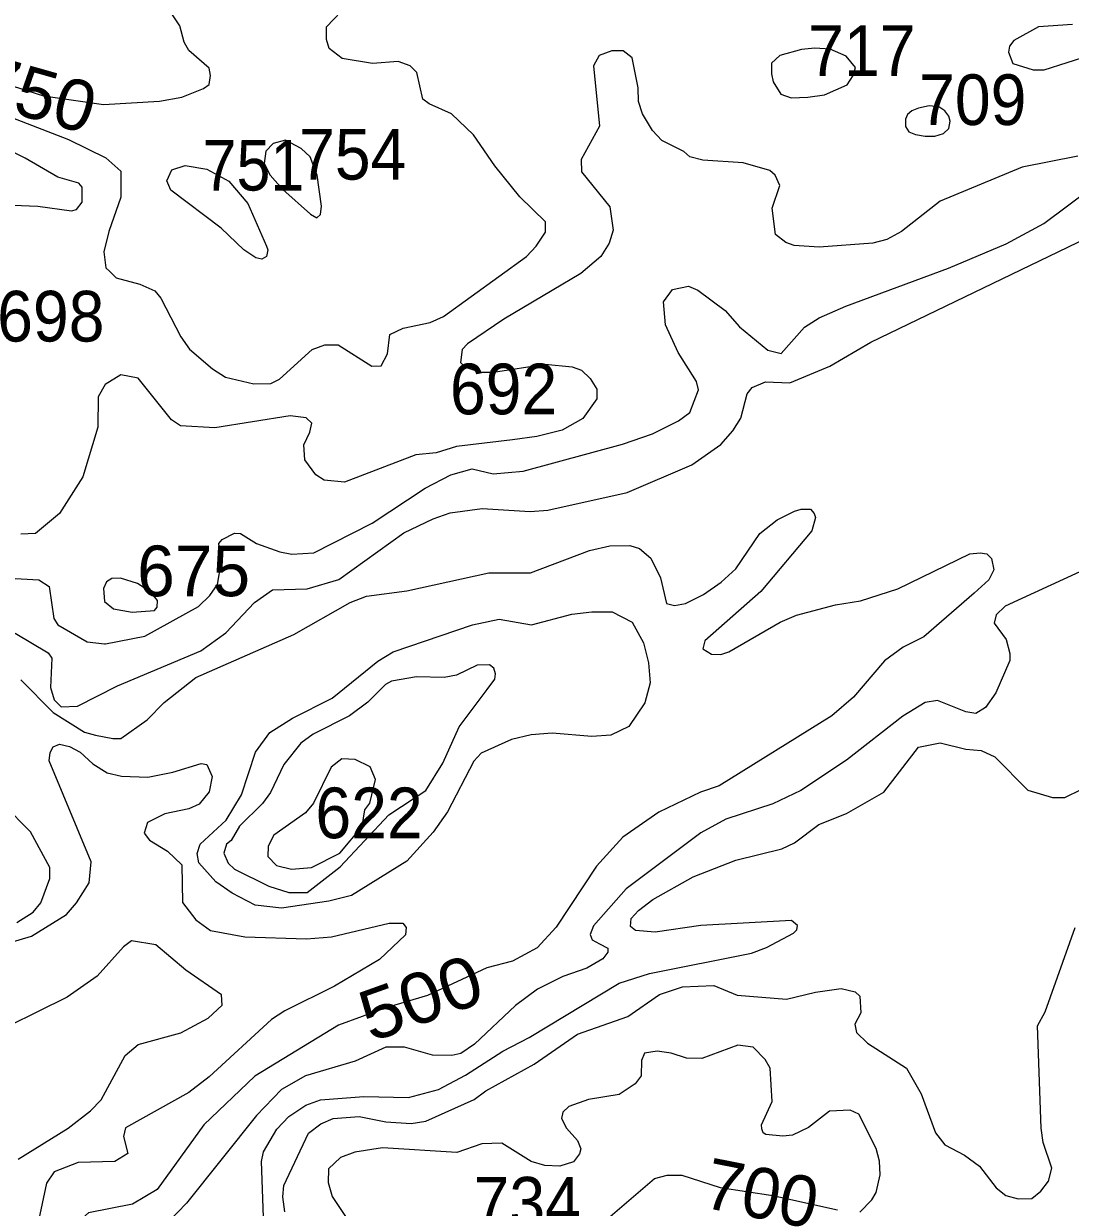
# Model space of a CAD drawing. Extents: x 499.9 to 555.3, y 9281.5 to 9336.8.
# Drawn here: x 539.393 to 542.701, y 9298.961 to 9302.7 of the extents above; entities that cross this region are included whole.
import ezdxf
from ezdxf.enums import TextEntityAlignment as Align

# ---------------------------------------------------------------- set-up
doc = ezdxf.new("R2010")
doc.units = 0
doc.header["$LTSCALE"] = 0.064
doc.layers.add('1', color=7, linetype='Continuous', lineweight=25)
doc.layers.add('2', color=7, linetype='Continuous', lineweight=13)
doc.layers.add('21', color=7, linetype='Continuous')
doc.layers.add('61', color=7, linetype='Continuous')

msp = doc.modelspace()

# ---------------------------------------------------------------- linework, layer by layer
at = {"layer": '1'}
for points in [[(539.3094, 9302.5175), (539.4558, 9302.4719), (539.6454, 9302.4446), (539.8226, 9302.4545), (539.8926, 9302.4671), (539.9617, 9302.4944), (539.9789, 9302.5073), (539.9835, 9302.5353), (539.9789, 9302.5594), (539.9155, 9302.6146), (539.9005, 9302.6411), (539.8868, 9302.6932), (539.8411, 9302.7602), (539.8248, 9302.8301), (539.7819, 9302.9001), (539.7231, 9302.959), (539.5872, 9303.0698), (539.529, 9303.131), (539.4177, 9303.2807), (539.3787, 9303.2971)], [(539.3846, 9300.6267), (539.4859, 9300.5243), (539.5854, 9300.4617), (539.6199, 9300.4526), (539.6745, 9300.4413), (539.7007, 9300.4421), (539.7835, 9300.5002), (539.837, 9300.5555), (539.937, 9300.6342), (540.2465, 9300.7702), (540.4251, 9300.8709), (540.476, 9300.8915), (540.604, 9300.9077), (540.8634, 9300.9646), (540.9948, 9300.965), (541.1807, 9301.0357), (541.2454, 9301.0506), (541.3091, 9301.0508), (541.3396, 9301.0423), (541.3755, 9301.0116), (541.4053, 9300.9489), (541.4245, 9300.8685), (541.4493, 9300.8617), (541.485, 9300.8679), (541.5413, 9300.8969), (541.597, 9300.9352), (541.6437, 9300.9777), (541.7197, 9301.0895), (541.7738, 9301.1323), (541.8294, 9301.1596), (541.8498, 9301.1659), (541.8799, 9301.166), (541.891, 9301.1526), (541.8952, 9301.1399), (541.8838, 9301.0979), (541.7221, 9300.9059), (541.5461, 9300.7504), (541.5398, 9300.7248), (541.5671, 9300.7076), (541.5957, 9300.7071), (541.6218, 9300.715), (541.7842, 9300.8089), (541.8352, 9300.8311), (541.9583, 9300.8637), (542.037, 9300.8761), (542.1558, 9300.914), (542.3827, 9301.0251), (542.4156, 9301.0283), (542.4364, 9301.0248), (542.4518, 9301.01), (542.4585, 9300.9744), (542.4431, 9300.9426), (542.3969, 9300.9012), (542.2378, 9300.7625), (542.1719, 9300.7304), (542.1131, 9300.6873), (542.0154, 9300.5724), (541.9472, 9300.5134), (541.5907, 9300.2922), (541.532, 9300.2722), (541.3998, 9300.2092), (541.2867, 9300.1298), (541.2033, 9300.0385), (541.0756, 9299.8462), (541.0162, 9299.7804), (540.9382, 9299.7382), (540.8569, 9299.7175), (540.6693, 9299.6305), (540.5379, 9299.5915), (540.388, 9299.5367), (540.1236, 9299.3757)], [(539.3714, 9299.8604), (539.4231, 9299.8933), (539.4476, 9299.9225), (539.476, 9299.9996), (539.4761, 9300.0338), (539.4152, 9300.1465), (539.329, 9300.2329)], [(540.1236, 9299.3757), (539.9621, 9299.2217), (539.8153, 9299.0169), (539.7366, 9298.9706), (539.5983, 9298.9436), (539.5418, 9298.8941)]]:
    msp.add_lwpolyline(points, dxfattribs=at)
for points in [[(540.2126, 9302.1754), (540.2991, 9302.0978), (540.3195, 9302.0866), (540.3314, 9302.0973), (540.3342, 9302.1228), (540.3205, 9302.2212), (540.298, 9302.2789), (540.2704, 9302.3049), (540.2208, 9302.3312), (540.1818, 9302.3212), (540.1587, 9302.2969), (540.1532, 9302.2579), (540.1725, 9302.2213)], [(540.0174, 9302.0538), (539.8579, 9302.174), (539.8457, 9302.2035), (539.8619, 9302.2374), (539.9032, 9302.2512), (539.9719, 9302.2396), (540.0415, 9302.2016), (540.1011, 9302.1316), (540.1604, 9301.997), (540.1649, 9301.9853), (540.1605, 9301.9637), (540.1454, 9301.9556), (540.1265, 9301.9598), (540.0892, 9301.9853)], [(540.7323, 9300.2097), (540.6867, 9300.1464), (540.604, 9300.0548), (540.429, 9299.946), (540.3574, 9299.9277), (540.208, 9299.9058), (540.1245, 9299.9148), (540.052, 9299.9531), (540.0007, 9299.9888), (539.9467, 9300.049), (539.9414, 9300.0783), (539.951, 9300.1085), (540.0333, 9300.1839), (540.0817, 9300.2633), (540.1253, 9300.3987), (540.1715, 9300.4612), (540.2428, 9300.5059), (540.3677, 9300.5686), (540.5119, 9300.6858), (540.5603, 9300.7155), (540.8118, 9300.8009), (540.8961, 9300.8183), (540.9979, 9300.8012), (541.1254, 9300.8343), (541.1889, 9300.8423), (541.2526, 9300.8421), (541.3156, 9300.8091), (541.3514, 9300.7444), (541.3673, 9300.6807), (541.3733, 9300.6179), (541.3559, 9300.5543), (541.305, 9300.4795), (541.2485, 9300.452), (541.1881, 9300.4478), (541.0637, 9300.4587), (540.9971, 9300.4537), (540.9351, 9300.4382), (540.8389, 9300.3949), (540.8161, 9300.3705)]]:
    msp.add_lwpolyline(points, close=True, dxfattribs=at)
at = {"layer": '2'}
for points in [[(539.8899, 9301.7104), (539.9177, 9301.6715), (539.9904, 9301.6092), (540.0314, 9301.5833), (540.1202, 9301.5617), (540.1738, 9301.5633), (540.2021, 9301.5762), (540.3051, 9301.6709), (540.3447, 9301.6855), (540.3875, 9301.6853), (540.4936, 9301.6182), (540.5231, 9301.6191), (540.5427, 9301.6564), (540.55, 9301.7178), (540.5924, 9301.7378), (540.6779, 9301.7555), (540.7203, 9301.7746), (540.982, 9301.9644), (541.0127, 9301.9968), (541.0419, 9302.0412), (541.0425, 9302.0733), (540.9614, 9302.1522), (540.8823, 9302.2502), (540.8149, 9302.3479), (540.7448, 9302.4146), (540.6748, 9302.4458), (540.6548, 9302.4606), (540.6355, 9302.5455), (540.614, 9302.5664), (540.577, 9302.5802), (540.4958, 9302.574), (540.3996, 9302.59), (540.3588, 9302.6213), (540.3503, 9302.6495), (540.3506, 9302.69), (540.4186, 9302.7615)], [(542.7073, 9302.6967), (542.6, 9302.6897), (542.522, 9302.6462), (542.5083, 9302.6285), (542.5055, 9302.6098), (542.5189, 9302.5739), (542.5831, 9302.5534), (542.618, 9302.5533), (542.7632, 9302.5997)], [(542.724, 9302.2814), (542.5479, 9302.2462), (542.2894, 9302.1393), (542.1676, 9302.0433), (542.1209, 9302.0183), (542.077, 9302.0058), (541.9065, 9301.9931), (541.8274, 9301.9991), (541.8013, 9302.0086), (541.7689, 9302.034), (541.7589, 9302.1165), (541.7827, 9302.188), (541.7681, 9302.2206), (541.7505, 9302.2355), (541.6665, 9302.2597), (541.5391, 9302.2684), (541.4979, 9302.2787), (541.4794, 9302.2955), (541.4094, 9302.3301), (541.38, 9302.3623), (541.3491, 9302.4149), (541.3357, 9302.4538), (541.3352, 9302.4967), (541.3159, 9302.5913), (541.2874, 9302.6137), (541.2519, 9302.6134), (541.2121, 9302.5995), (541.1937, 9302.5661), (541.2127, 9302.3756), (541.1545, 9302.2706), (541.1554, 9302.2318), (541.2458, 9302.1208), (541.2555, 9302.0472), (541.2429, 9302.0058), (541.2175, 9301.9644), (541.1533, 9301.9105), (540.9104, 9301.766), (540.7957, 9301.6886), (540.7783, 9301.6708), (540.7731, 9301.6291), (540.7896, 9301.6143), (540.8364, 9301.5984), (540.8778, 9301.5985), (541.0407, 9301.6236), (541.1269, 9301.6153), (541.1556, 9301.6048), (541.1833, 9301.5787), (541.2046, 9301.5456), (541.2045, 9301.5141), (541.1605, 9301.4527), (541.0947, 9301.4153)], [(539.2537, 9302.4418), (539.5344, 9302.3332), (539.6524, 9302.276), (539.7, 9302.2334), (539.7, 9302.1513), (539.6621, 9302.043), (539.6466, 9301.979), (539.653, 9301.9284), (539.6639, 9301.9177)], [(539.3601, 9302.1267), (539.4375, 9302.1236), (539.5447, 9302.1081), (539.5597, 9302.1127), (539.5776, 9302.1359), (539.5782, 9302.1834), (539.5675, 9302.1953), (539.5012, 9302.2146), (539.3977, 9302.2751), (539.3156, 9302.3145)], [(539.3293, 9300.9493), (539.4406, 9300.9425), (539.4736, 9300.922), (539.4888, 9300.8204), (539.5011, 9300.8006), (539.5943, 9300.7471), (539.6483, 9300.7405), (539.6516, 9300.7406), (539.7757, 9300.7653), (539.9453, 9300.8586), (539.9818, 9300.8936), (540.0056, 9300.9279), (540.0174, 9300.996), (540.0101, 9301.0576), (540.0199, 9301.0702), (540.0589, 9301.0904), (540.0785, 9301.0897), (540.129, 9301.058), (540.2024, 9301.0309), (540.2404, 9301.0238), (540.3097, 9301.0285), (540.4944, 9301.1221), (540.662, 9301.2329), (540.7427, 9301.2749), (540.8103, 9301.2939), (540.8764, 9301.278), (540.9713, 9301.2857), (541.2852, 9301.371), (541.3799, 9301.4042), (541.4627, 9301.4456), (541.4978, 9301.4718), (541.526, 9301.5434), (541.5198, 9301.5696), (541.4618, 9301.6605), (541.4213, 9301.7487), (541.4152, 9301.821), (541.4436, 9301.8598), (541.4941, 9301.8705), (541.5233, 9301.8577), (541.6102, 9301.7939), (541.6553, 9301.7416), (541.7444, 9301.6681), (541.7872, 9301.6577), (541.8602, 9301.7409), (541.9067, 9301.7702), (541.9909, 9301.807), (542.3151, 9301.9275), (542.4979, 9302.0045), (542.6172, 9302.0683), (542.7669, 9302.1795)], [(540.5946, 9301.0917), (540.6874, 9301.136), (540.7409, 9301.1543), (540.8421, 9301.1685), (540.994, 9301.1591), (541.0497, 9301.1624), (541.2999, 9301.2186), (541.5043, 9301.3065), (541.5963, 9301.3708), (541.6346, 9301.4138), (541.659, 9301.4534), (541.6791, 9301.5307), (541.6957, 9301.5505), (541.7373, 9301.5678), (541.8143, 9301.5654), (541.9401, 9301.6175), (542.0707, 9301.6937), (542.7823, 9302.0369)], [(539.6639, 9301.9177), (539.685, 9301.897), (539.7607, 9301.8772), (539.8076, 9301.8553), (539.8268, 9301.8328), (539.8899, 9301.7104)], [(540.6324, 9301.3377), (540.4067, 9301.2516), (540.343, 9301.2573), (540.3163, 9301.2744), (540.2818, 9301.3222), (540.2788, 9301.3691), (540.2975, 9301.4089), (540.3036, 9301.4375), (540.2854, 9301.4544), (540.2354, 9301.4612), (539.9977, 9301.4233), (539.8884, 9301.4293), (539.8604, 9301.4486), (539.7554, 9301.58), (539.7003, 9301.5908), (539.6504, 9301.56), (539.6291, 9301.5213), (539.6271, 9301.4253), (539.5801, 9301.268), (539.5061, 9301.1521), (539.4302, 9301.0893), (539.3837, 9301.0871)], [(541.0947, 9301.4153), (541.0151, 9301.3952), (540.9382, 9301.3848), (540.7612, 9301.3638), (540.6966, 9301.3445), (540.6324, 9301.3377)], [(540.0316, 9300.7757), (540.1227, 9300.8711), (540.1799, 9300.9118), (540.2889, 9300.9142), (540.3893, 9300.9439), (540.5946, 9301.0917)], [(542.7302, 9300.9685), (542.4942, 9300.8597), (542.4661, 9300.8319), (542.4598, 9300.806), (542.4973, 9300.7539), (542.5098, 9300.7102), (542.5099, 9300.6879), (542.4653, 9300.5861), (542.4326, 9300.5397), (542.4019, 9300.5212), (542.37, 9300.5258), (542.2808, 9300.562), (542.2418, 9300.5554), (542.1708, 9300.5122), (541.9934, 9300.3732), (541.8495, 9300.2771), (541.76, 9300.2356), (541.6124, 9300.1865), (541.533, 9300.1433), (541.297, 9299.9664), (541.1935, 9299.85), (541.1829, 9299.8223), (541.1896, 9299.8063), (541.2131, 9299.793), (541.2391, 9299.78), (541.2395, 9299.7665), (541.2238, 9299.7459), (541.1723, 9299.7168), (541.0967, 9299.69), (541.0173, 9299.6499), (540.9469, 9299.5989), (540.8178, 9299.476), (540.7746, 9299.4473), (540.7457, 9299.4402), (540.6854, 9299.4414), (540.5968, 9299.4666), (540.5381, 9299.4671), (540.4402, 9299.4224), (540.2842, 9299.3761), (540.208, 9299.333), (540.1294, 9299.2513), (539.9077, 9298.9739), (539.765, 9298.8263)], [(539.3663, 9300.7744), (539.471, 9300.712), (539.4825, 9300.6951), (539.4783, 9300.6029), (539.4899, 9300.564), (539.5121, 9300.5414), (539.5631, 9300.5442), (539.6895, 9300.6083), (539.9526, 9300.719), (540.0316, 9300.7757)], [(541.3712, 9299.6997), (541.6927, 9299.7635), (541.7403, 9299.7811), (541.8263, 9299.8265), (541.8362, 9299.8376), (541.8381, 9299.851), (541.8199, 9299.8665), (541.5327, 9299.8507), (541.3888, 9299.8301), (541.3262, 9299.8357), (541.3104, 9299.8478), (541.3127, 9299.8727), (541.3355, 9299.8985), (541.3816, 9299.9335), (541.5089, 9300.0043), (541.6434, 9300.0574), (541.7891, 9300.0934), (541.8287, 9300.1119), (541.9061, 9300.1702), (541.9928, 9300.2048), (542.1117, 9300.2724), (542.2211, 9300.4142), (542.2896, 9300.4285), (542.3699, 9300.4079), (542.4183, 9300.4042), (542.4621, 9300.3838), (542.5662, 9300.2784), (542.6444, 9300.2551), (542.6832, 9300.2551), (542.7343, 9300.2806)], [(539.2433, 9299.7662), (539.4184, 9299.8171), (539.5289, 9299.8858), (539.5603, 9299.9224), (539.6006, 9299.9854), (539.6069, 9300.0527), (539.4738, 9300.3715), (539.4768, 9300.3974), (539.4867, 9300.4153), (539.5064, 9300.4234), (539.5376, 9300.4168), (539.5719, 9300.3981), (539.6117, 9300.3617), (539.6572, 9300.3335), (539.7025, 9300.323), (539.7853, 9300.3191), (539.8646, 9300.3353), (539.9538, 9300.3624), (539.9717, 9300.3592), (539.9885, 9300.3218), (539.9797, 9300.2728), (539.9473, 9300.2347), (539.915, 9300.2198), (539.8394, 9300.2039), (539.7849, 9300.1763), (539.7743, 9300.1427), (539.7911, 9300.1204), (539.8472, 9300.0862), (539.8931, 9300.0427), (539.8956, 9299.9236), (539.9374, 9299.8687), (539.9835, 9299.8353), (540.0916, 9299.8157), (540.287, 9299.8095), (540.3663, 9299.8154), (540.5484, 9299.8585), (540.5917, 9299.8587), (540.6014, 9299.8444), (540.5994, 9299.8217), (540.5178, 9299.7441), (540.3749, 9299.6594), (540.218, 9299.5818), (540.1767, 9299.5542), (539.979, 9299.3729), (539.9151, 9299.3235), (539.7151, 9299.2117), (539.709, 9299.1848), (539.7226, 9299.1305), (539.6816, 9299.1059), (539.5656, 9299.1026), (539.4899, 9299.0728), (539.4653, 9299.0373), (539.4381, 9298.9086)], [(540.5372, 9299.2315), (540.6173, 9299.2253), (540.6644, 9299.2336), (540.8165, 9299.3018), (540.8538, 9299.329), (541.0066, 9299.4135), (541.1437, 9299.5081), (541.3028, 9299.5641), (541.4029, 9299.633), (541.4754, 9299.6574), (541.5744, 9299.6613), (541.6474, 9299.6306), (541.8041, 9299.6185), (541.8957, 9299.6406), (541.9765, 9299.6516), (542.0202, 9299.6417), (542.0359, 9299.6283), (542.0386, 9299.5755), (542.0201, 9299.5394), (542.0253, 9299.5128), (542.0594, 9299.479), (542.183, 9299.4005), (542.2294, 9299.3199), (542.2741, 9299.1958), (542.3035, 9299.1583), (542.3661, 9299.1254), (542.4135, 9299.0905), (542.4662, 9299.0225), (542.4967, 9298.9983), (542.5362, 9298.9882), (542.5793, 9298.9886), (542.607, 9299.0121), (542.6314, 9299.044), (542.6419, 9299.0842), (542.6152, 9299.1657), (542.6087, 9299.2109), (542.5965, 9299.5347), (542.6213, 9299.5787), (542.7161, 9299.8453)], [(539.3763, 9299.1127), (539.5337, 9299.211), (539.6043, 9299.2656), (539.6381, 9299.3), (539.7137, 9299.44), (539.755, 9299.4754), (539.8902, 9299.5118), (539.9762, 9299.558), (540.0204, 9299.5995), (540.018, 9299.632), (539.9052, 9299.7103), (539.8112, 9299.7896), (539.7334, 9299.8029), (539.7083, 9299.7833), (539.6257, 9299.6907), (539.5304, 9299.6244), (539.2529, 9299.4877)], [(540.7044, 9299.3333), (540.7894, 9299.3787), (540.9072, 9299.4544), (540.9907, 9299.4978), (541.275, 9299.6693), (541.3712, 9299.6997)], [(542.0351, 9298.9459), (542.0733, 9298.9844), (542.0873, 9299.0074), (542.0992, 9299.0638), (542.0975, 9299.1067), (542.0868, 9299.1466), (542.0322, 9299.2553), (542.0053, 9299.268), (541.9399, 9299.2651), (541.8733, 9299.2126), (541.8229, 9299.189), (541.7919, 9299.1855), (541.7382, 9299.1906), (541.7298, 9299.1964), (541.7259, 9299.2086), (541.725, 9299.2213), (541.7588, 9299.2955), (541.7521, 9299.4003), (541.7363, 9299.4274), (541.6987, 9299.4664), (541.6497, 9299.4733), (541.5359, 9299.4307), (541.4881, 9299.4323), (541.4396, 9299.4482), (541.3945, 9299.4542), (541.3548, 9299.4477), (541.3451, 9299.4251), (541.3447, 9299.3766), (541.3251, 9299.3506), (541.2749, 9299.3178), (541.1777, 9299.301), (541.1159, 9299.2791), (541.0971, 9299.2611), (541.0932, 9299.2415), (541.108, 9299.211), (541.1437, 9299.1717), (541.1536, 9299.1459), (541.15, 9299.1303), (541.1304, 9299.1049), (541.0873, 9299.091), (541.0401, 9299.0931), (540.9966, 9299.1054), (540.9038, 9299.1632), (540.8411, 9299.1616), (540.7616, 9299.1346), (540.5268, 9299.1488), (540.4395, 9299.1349), (540.3939, 9299.1188), (540.3567, 9299.0828), (540.3551, 9299.0391), (540.3675, 9298.9953), (540.462, 9298.8544)], [(540.1513, 9298.9295), (540.1449, 9299.1058), (540.1515, 9299.1361), (540.1927, 9299.2078), (540.2309, 9299.2475), (540.285, 9299.284), (540.3314, 9299.3003), (540.4677, 9299.3112), (540.6096, 9299.3081), (540.7044, 9299.3333)], [(540.2151, 9299.0294), (540.2931, 9299.1949), (540.332, 9299.2247), (540.3717, 9299.2412), (540.4536, 9299.2474), (540.5372, 9299.2315)], [(541.2463, 9298.9321), (541.3863, 9299.0517), (541.427, 9299.0627), (541.473, 9299.0626), (541.5939, 9299.0233), (541.76, 9298.9987), (541.9644, 9298.9532)], [(540.2184, 9298.9468), (540.2121, 9298.9936), (540.2151, 9299.0294)]]:
    msp.add_lwpolyline(points, dxfattribs=at)
for points in [[(541.8706, 9302.4673), (541.9233, 9302.4751), (541.9949, 9302.5058), (542.0145, 9302.5357), (542.0217, 9302.5611), (541.992, 9302.597), (541.9416, 9302.6195), (541.8937, 9302.6223), (541.8508, 9302.6176), (541.7823, 9302.5991), (541.756, 9302.5745), (541.7563, 9302.5409), (541.762, 9302.5156), (541.7854, 9302.4769), (541.8183, 9302.4648)], [(542.2113, 9302.3496), (542.2417, 9302.344), (542.2721, 9302.344), (542.2998, 9302.3523), (542.3164, 9302.3689), (542.3205, 9302.3911), (542.3164, 9302.4077), (542.3039, 9302.4243), (542.2846, 9302.4367), (542.2542, 9302.4395), (542.2212, 9302.4329), (542.1993, 9302.4244), (542.1859, 9302.4126), (542.1799, 9302.3984), (542.1795, 9302.3745), (542.1905, 9302.3579)], [(539.6769, 9300.8515), (539.7357, 9300.8403), (539.8071, 9300.8457), (539.815, 9300.8561), (539.8162, 9300.8778), (539.7955, 9300.904), (539.7525, 9300.9311), (539.699, 9300.9484), (539.6719, 9300.9471), (539.6546, 9300.9362), (539.6459, 9300.9159), (539.6491, 9300.874)], [(540.1684, 9299.9755), (540.2309, 9299.9548), (540.2886, 9299.9554), (540.3932, 9300.0359), (540.5467, 9300.201), (540.6643, 9300.277), (540.7182, 9300.3639), (540.7692, 9300.4784), (540.8583, 9300.5964), (540.8825, 9300.629), (540.8846, 9300.6461), (540.8794, 9300.6643), (540.8647, 9300.6745), (540.8261, 9300.6731), (540.7608, 9300.6419), (540.7218, 9300.634), (540.6349, 9300.6368), (540.555, 9300.6223), (540.5361, 9300.6125), (540.4812, 9300.5564), (540.4229, 9300.5131), (540.3079, 9300.4559), (540.2694, 9300.4272), (540.215, 9300.36), (540.1731, 9300.2712), (540.1479, 9300.236), (540.0755, 9300.1646), (540.0491, 9300.1196), (540.0337, 9300.1083), (540.0262, 9300.0796), (540.0399, 9300.0482), (540.0596, 9300.0286)], [(540.3028, 9300.0344), (540.3921, 9300.0792), (540.4626, 9300.1633), (540.4717, 9300.2168), (540.4874, 9300.2373), (540.5046, 9300.3127), (540.4884, 9300.3519), (540.4409, 9300.3758), (540.3986, 9300.3774), (540.365, 9300.3507), (540.3094, 9300.2379), (540.2841, 9300.2068), (540.184, 9300.136), (540.1659, 9300.102), (540.1649, 9300.0687), (540.1925, 9300.0411), (540.2397, 9300.0291)]]:
    msp.add_lwpolyline(points, close=True, dxfattribs=at)

# ---------------------------------------------------------------- texts
at = {"layer": '21'}
for s, width, p in [('717', 0.95, (541.8722, 9302.5345)), ('709', 0.95, (542.2227, 9302.3794)), ('754', 0.95, (540.2633, 9302.207)), ('751', 0.9, (539.9587, 9302.1725)), ('698', 0.95, (539.3094, 9301.6956)), ('692', 0.95, (540.7402, 9301.4657)), ('622', 0.95, (540.315, 9300.1268)), ('734', 0.95, (540.8149, 9298.8971))]:
    msp.add_text(s, height=0.16, dxfattribs=dict(at, width=width)).set_placement(p)
msp.add_text('675', height=0.16, dxfattribs=at).set_placement((539.7518, 9300.8911))
at = {"layer": '61'}
for s, rotation, width, p in [('750', 344.141, 1.05, (539.4131, 9302.4009)), ('500', 19.654, 1.1, (540.6748, 9299.5475))]:
    msp.add_text(s, height=0.16, rotation=rotation, dxfattribs=dict(at, width=width)).set_placement(p, align=Align.CENTER)
msp.add_text('700', height=0.16, rotation=348.821, dxfattribs=at).set_placement((541.7097, 9298.9271), align=Align.CENTER)

doc.saveas('drawing.dxf')
